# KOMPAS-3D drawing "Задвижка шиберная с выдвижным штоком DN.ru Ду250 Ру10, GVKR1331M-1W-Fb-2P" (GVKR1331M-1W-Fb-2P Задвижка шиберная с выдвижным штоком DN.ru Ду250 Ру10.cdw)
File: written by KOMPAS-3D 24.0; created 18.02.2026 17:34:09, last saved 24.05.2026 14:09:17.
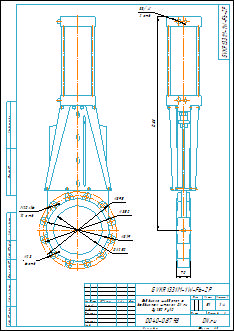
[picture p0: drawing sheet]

Document properties: Автор: R2D2; Форматы листов документа: A3; Полное имя файла: GVKR1331M-1W-Fb-2P Задвижка шиберная с выдвижным штоком DN.ru Ду250 Ру10.m3d; Масса: 51; Наименование: Задвижка шиберная с выдвижным штоком DN.ru Ду250 Ру10; Количество листов документа: 1; Примечание: D040-08798

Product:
- Part/product: Задвижка шиберная с выдвижным штоком DN.ru Ду250 Ру10  | designation GVKR1331M-1W-Fb-2P
    Масса: 51
    Раздел спецификации: Прочие изделия
    Примечание: D040-08798

Views: Вид 1, Спереди, Проекционный вид 2
Referenced files in E:\Работа\Зайцев\GVKR1331N-2W-Fb-S Задвижка шиберная с выдвижным штоком DN.ru Ду50-300 Ру10\DN50\: GVKR1331N-2W-Fb-S Задвижка шиберная DN.ru Ду50 Ру10.m3d
Referenced files in E:\Работа\Зайцев\GVKR1331M-1W-Fb-2P Задвижка шиберная с выдвижным штоком DN.ru Ду50-300 Ру16-10-6 с пневмоприводом\исходные материалы\DN250\DN250\: GVKR1331M-1W-Fb-2P Задвижка шиберная с выдвижным штоком DN.ru Ду250 Ру10.m3d
Referenced files in E:\Работа\Зайцев\Для компаса\: чертеж DN.ru А3.cdt
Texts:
  GVKR1331M-1W-Fb-2P
  чертеж DN.ru А3.cdt
  Задвижка шиберная с
  выдвижным штоком DN.ru
  Ду250 Ру10
  Задвижка шиберная с выдвижным штоком DN.ru Ду250 Ру10
  GVKR1331M-1W-Fb-2P Задвижка шиберная с выдвижным штоком DN.ru Ду250 Ру10
Dimensions and other numbers on the sheet: 0; 3; 2; 4; 20; 12 отв.; 23; 6 отв.; 395; 319; 350; 250; 2 отв.; 70; 1088; 1:4; 1; 51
